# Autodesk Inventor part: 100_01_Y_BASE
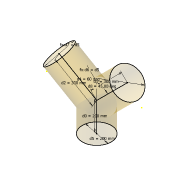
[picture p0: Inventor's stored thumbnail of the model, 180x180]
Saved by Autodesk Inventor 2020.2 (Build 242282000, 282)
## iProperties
Created: 2011-01
Part Number: 100_01_Y_BASE
Document SubType Name: Modeling
Designer: F.Stasiak
Density: 1 g/cm^3
Material: Ogólny
Appearance: Domyślna
Catalog Web Link: www.expertbooks.pl
Manager: www.cadconsulting.pl
Company: Fabian Stasiak CAD Consulting
Author: F.Stasiak
Subject: Zbiór ćwiczeń. Autodesk Inventor 2020. Kurs zaawansowany
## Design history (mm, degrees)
sketch "KĄTY I DŁUGOŚCI RUR"
  geometry: L1 (0, 0)-(0, 200); L2 (0, 200)-(212.132, 412.132); L3 (0, 200)-(-259.808, 350)
  constraints: 6 end point, 1 vertical
  dimensions: "d0" = 200 distance of L1.start L1.end; "d1" = 300 distance of L1.end L2.end; "d2" = 300 distance of L1.end L3.end; "d4" = 60 deg angle of L1 L3; "d8" = 45 deg angle of L1 L2
sketch "ŚREDNICA RURY 1 = d5"
  geometry: C1 r 100 at (0, 0); 1 further point
  constraints: 1 centre point, 1 coincident
  dimensions: "d5" = 200 diameter of C1
node "Płaszczyzna konstrukcyjna1"
sketch "ŚREDNICA RURY 2 = d5"
  geometry: C1 r 100 at (0, 0); 2 further points
  constraints: 1 centre point, 1 coincident
  dimensions: "d6" = 200 diameter of C1 (= d5)
node "Płaszczyzna konstrukcyjna2"
sketch "ŚREDNICA RURY 3 = d5"
  geometry: C1 r 100 at (0, 0); 2 further points
  constraints: 1 centre point, 1 coincident
  dimensions: "d7" = 200 diameter of C1 (= d5)
feature "RURA 1" dims "d9" = 200 (= d0), "d10" = 0
feature "RURA 2" dims "d13" = 300 (= d1), "d14" = 0
feature "RURA 3" dims "d11" = 300 (= d2), "d12" = 0
feature "Utnij1"
feature "Utnij2"
feature "Utnij3"
feature "Utnij4"
feature "Utnij5"
feature "Utnij6"
body "Srf1"
body "Srf3"
body "Srf2"
